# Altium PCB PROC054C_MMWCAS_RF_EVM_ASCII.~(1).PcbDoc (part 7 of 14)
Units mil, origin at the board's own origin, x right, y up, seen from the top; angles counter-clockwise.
Board outline 6299.21 x 5370.07 mil, 8 copper layers (L1 TOP, L2 GND, L3 SIGNAL 1, L4 GND, L5 SIGNAL 2, L6 SIGNAL 3, L7 GND, L8 BOTTOM), stack 53.5 mil thick; 775 components, 552 nets, 2648 pads, 7845 vias.
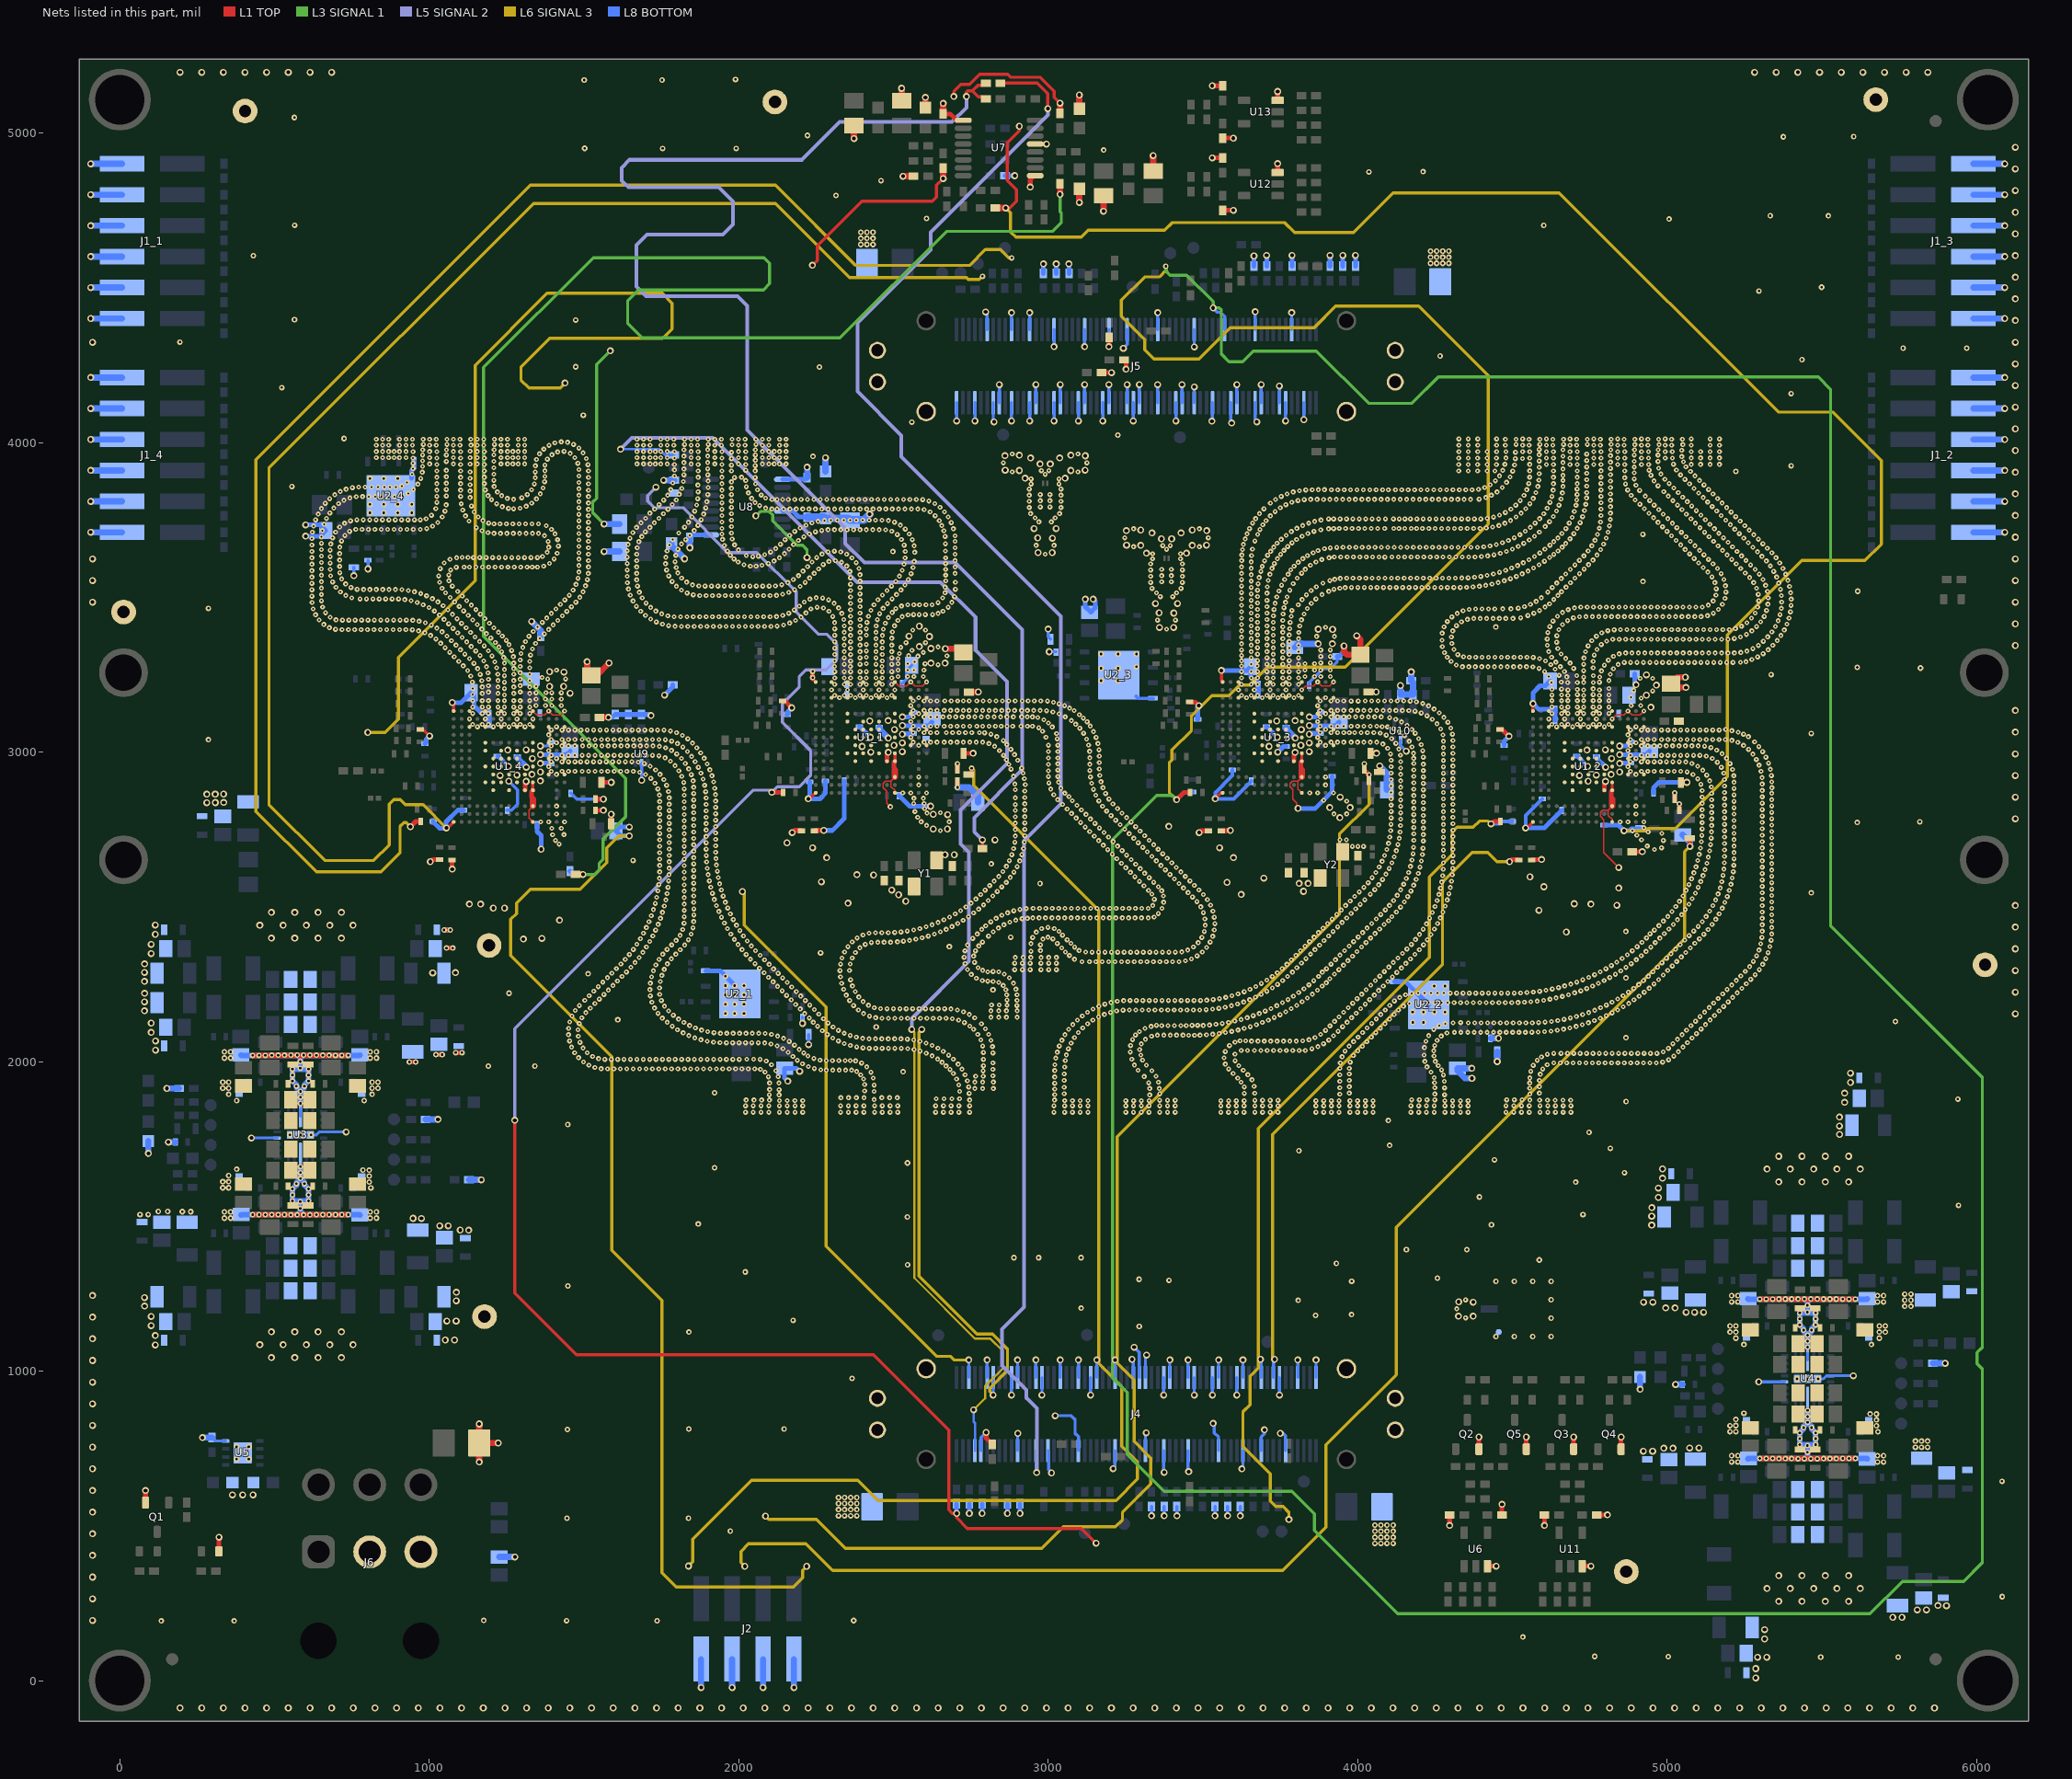
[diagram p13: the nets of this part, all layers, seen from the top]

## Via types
v1: diameter 13.77/15.74 (per signal layer), hole 5.9, L1 TOP to L2 GND, tented both sides, 5522 vias
v2: diameter 22.4, hole 12.2, L1 TOP to L8 BOTTOM, tented both sides, 1522 vias
v3: diameter 18, hole 8, L1 TOP to L8 BOTTOM, tented both sides, 727 vias
v4: diameter 18, hole 7.87, L1 TOP to L8 BOTTOM, tented top, 50 vias
v5: diameter 24, hole 12, L1 TOP to L8 BOTTOM, tented both sides, 13 vias
v6: diameter 19.68, hole 7.87, L1 TOP to L8 BOTTOM, tented top, 10 vias
v7: diameter 13.77/15.74 (per signal layer), hole 5.9, L1 TOP to L2 GND, tented top, 1 vias

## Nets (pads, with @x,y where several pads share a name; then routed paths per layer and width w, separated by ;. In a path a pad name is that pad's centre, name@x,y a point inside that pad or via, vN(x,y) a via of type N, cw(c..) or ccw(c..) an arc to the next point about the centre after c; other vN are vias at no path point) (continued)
EXT_40M_BUF_12XX_1_RS: R115.2 R116.1 R117.2 | length 5103.7
  L1 TOP w10.5: v2(2736.01,5118.34) 2736.01,5132.28 2739.95,5136.23 2755.17,5136.23 ; R116.1@2787.39,2687.68 v2(2787.39,2716.2) ; R117.2@2798.8,5110.83 2792.1,5117.53 2773.86,5117.53 2755.17,5136.23 ; R115.2@2798.8,5161.63 2792.1,5154.92 2773.86,5154.92 2755.17,5136.23
  L5 SIGNAL 2 w12: v2(2736.01,5118.34) 2736.01,5082.94 2688.92,5035.85 2325.79,5035.85 2203.61,4913.67 1647.48,4913.67 1621.64,4887.83 1621.64,4846.51 1643.5,4824.64 1935.89,4824.64 1981.39,4779.15 1981.39,4704.99 1948.57,4672.17 1703.22,4672.17 1669.07,4638.03 1669.07,4503.97 1700.69,4472.35 1996.53,4472.35 2026.88,4442 2026.88,4040.78 2343.82,3723.84 2343.82,3674.27 2405.7,3612.4 2698.66,3612.4 2916.05,3395.01 2916.05,2943.41 2761.03,2788.4 2761.03,2742.56 v2(2787.39,2716.2)
EXT_40MHZ_CLK_1V8: J4.74 R115.1 | length 5346.8
  L1 TOP w10.5: R115.1@2846.05,5161.63 2964.52,5161.63 2998.97,5127.18 v2(2998.97,5079.18)
  L5 SIGNAL 2 w12: v2(2963,672) 2963,879.16 2928.83,913.32 2928.83,939.35 2850.75,1017.44 2850.75,1135.48 2922.54,1207.28 2922.54,2714.26 3040.77,2832.49 3040.77,3438.97 2525.51,3954.23 2525.51,4022.96 2383.71,4164.76 2383.71,4386.29 2620.11,4622.69 2620.11,4679.15 2998.97,5058 v2(2998.97,5079.18)
  L8 BOTTOM w7.75: J4.74@2960.12,743.02 2960.12,674.88 v2(2963,672)
EXT_DIG_SYNC: J4.64 R142.1 | length 4659.5
  L5 SIGNAL 2 w12: v2(1617.95,3978.76) 1654.84,4015.65 1916.04,4015.65 2382.45,3549.24 2651.16,3549.24 2765.25,3435.16 2765.25,3329.43 2866.54,3228.13 2866.54,2963.13 2717.14,2813.73 2717.14,2702.79 2743.58,2676.34 2743.58,2323.96 2558.87,2139.25 v2(2558.87,2104.18)
  L6 SIGNAL 3 w6.9: v2(2558.87,2104.18) 2567.52,2095.53 2567.52,1300.82 2763.82,1104.52 2813.76,1104.52 2853.47,1064.81 2853.47,1008.41 2796.02,950.96 2796.02,912.03 v2(2759,875)
  L8 BOTTOM w7.75: v2(1617.95,3978.76) 1743.32,3978.76 1761.79,3960.29 R142.1@1791.14,3960.29 ; v2(2759,875) 2759,837 2763.27,832.73 J4.64@2763.27,743.02
GND: C1_1.2 C1_2.2 C1_3.2 C1_4.2 C2_1.2 C2_2.2 C2_3.2 C2_4.2 C3_1.2 C3_2.2 C3_3.2 C3_4.2 C4_1.2 C4_2.2 C4_3.2 C4_4.2 C5_1.2 C5_2.2 C5_3.2 C5_4.2 C6_1.2 C6_2.2 C6_3.2 C6_4.2 C7_1.2 C7_2.2 C7_3.2 C7_4.2 C8_1.2 C8_2.2 C8_3.2 C8_4.2 C9.2 C10.2 C11.2 C12.2 C13.2 C14.2 C15.2 C16.2 C17.2 C18.2 C19.2 C20.2 C21.2 C22.2 C23.2 C24.2 C25.2 C26.2 C27.2 C28.2 C29.2 C30.2 C31.2 C32.2 C33.2 C34.2 C35.2 C36.2 C39.2 C40.2 C41.2 C42.2 C43.2 C44.2 C45.2 C46.2 C47.2 C48.2 C51.2 C52.2 C53.2 C54.2 C55.2 C56.2 C57.2 C58.2 C59.2 C60.2 C61.2 C62.2 C63.2 C64.2 C65.2 C66.2 C67.2 C68.2 C69.2 C70.2 C71.2 C72.2 C73.2 C74.2 C75.2 C76.2 C77.2 C78.2 C79.2 C80.2 C81.2 C82.2 C83.2 C84.2 C85.2 C86.2 C87.2 C88.2 C89.2 C90.2 C91.2 C92.2 C93.2 C94.2 C97.2 C98.2 C99.2 C100.2 C101.2 C102.2 C103.2 C104.2 C105.2 C106.2 C109.2 C110.2 C111.2 C112.2 C113.2 C114.2 C115.2 C116.2 C117.2 C118.2 C119.2 C120.2 C121.2 C122.2 C123.2 C124.2 C125.2 C126.2 C127.2 C128_1.2 C128_2.2 C128_3.2 C128_4.2 C129_1.2 C129_2.2 C129_3.2 C129_4.2 C130_1.2 C130_2.2 C130_3.2 C130_4.2 C131_1.2 C131_2.2 C131_3.2 C131_4.2 C132_1.2 C132_2.2 C132_3.2 C132_4.2 C133_1.2 C133_2.2 C133_3.2 C133_4.2 C134_1.2 C134_2.2 C134_3.2 C134_4.2 C135_1.2 C135_2.2 C135_3.2 C135_4.2 C136_1.2 C136_2.2 C136_3.2 C136_4.2 C137_1.2 C137_2.2 C137_3.2 C137_4.2 C138_1.2 C138_2.2 C138_3.2 C138_4.2 C139_1.2 C139_2.2 C139_3.2 C139_4.2 C140_1.2 C140_2.2 C140_3.2 C140_4.2 C141_1.2 C141_2.2 C141_3.2 C141_4.2 C142_1.2 C142_2.2 C142_3.2 C142_4.2 C143_1.2 C143_2.2 C143_3.2 C143_4.2 C144_1.2 C144_2.2 C144_3.2 C144_4.2 C145_1.2 C145_2.2 C145_3.2 C145_4.2 C146_1.2 C146_2.2 C146_3.2 C146_4.2 C147_1.2 C147_2.2 C147_3.2 C147_4.2 C148_1.2 C148_2.2 C148_3.2 C148_4.2 C149.2 C150.2 C151.2 C152.2 C153.2 C154.2 C155.2 C156.2 C157.2 C158.2 C159.2 C160.2 C161.2 C162.2 C163.2 C164.2 C165.2 C166.2 C167.2 C168.1 C169.2 C170.2 C171.1 C172.2 C173.2 C174.2 C175.2 C176.2 C177.2 C178.1 C179.2 C180.1 C181.2 C182.2 C183.1 C184.2 C185.2 C186.2 C187.1 C188.2 C189.1 C190.2 C191.2 C192.2 C193.2 C194.2 C195.2 C196.2 C197.2 C198.2 C199.2 C200.2 C201.2 C202.2 C203.2 C204.2 C205.2 C206.2 C207.2 DS1.2 J1_1.2 J1_1.4 J1_1.6 J1_1.8 J1_1.10 J1_1.12 J1_2.2 J1_2.4 J1_2.6 J1_2.8 J1_2.10 J1_2.12 J1_3.2 J1_3.4 J1_3.6 J1_3.8 J1_3.10 J1_3.12 J1_4.2 J1_4.4 J1_4.6 J1_4.8 J1_4.10 J1_4.12 J2.2 J2.4 J2.6 J2.8 J3.2 J4.3 J4.6 J4.7 J4.10 J4.11 J4.14 J4.15 J4.18 J4.21 J4.23 J4.24 J4.27 J4.30 J4.31 J4.32 J4.35 J4.36 J4.39 J4.40 J4.43 J4.44 J4.47 J4.48 J4.51 J4.53 J4.54 J4.57 J4.60 J4.65 J4.71 J4.76 J4.81 J4.87 J4.92 J4.95 J4.99 J4.104 J4.108 J4.111 J4.115 J4.MH1 J4.MH2 J4.P1 J4.P2 J5.6 J5.10 J5.13 J5.17 J5.22 J5.26 J5.29 J5.34 J5.40 J5.45 J5.50 J5.56 J5.61 J5.64 J5.67 J5.68 J5.70 J5.73 J5.74 J5.77 J5.78 J5.81 J5.82 J5.85 J5.86 J5.89 J5.90 J5.91 J5.94 J5.97 J5.98 J5.100 J5.103 J5.106 J5.107 J5.110 J5.111 J5.114 J5.115 J5.118 J5.MH1 J5.MH2 J5.P3 J5.P4 J6.2 J6.3 Q1.2 Q2.2 Q3.2 Q4.2 Q5.2 R16_1.1 R16_2.1 R16_3.1 R16_4.1 R17_1.1 R17_2.1 R17_3.1 R17_4.1 R18_1.1 R18_2.1 R18_3.1 R18_4.1 R20.1 R36.1 R39.1 R40.1 R41.1 R42.1 R55.1 R57.1 R58.1 R60.1 R63.1 R64.1 R65.1 R66.1 R79.2 R81.1 R82.2 R83.2 R84.2 R85.2 R110.1 R111.1 R113.1 R124.1 R128.2 R129.1 R130.1 R131.1 R139.1 R144.1 R165.1 R182_1.1 R182_2.1 R182_3.1 R182_4.1 R183_1.1 R183_2.1 R183_3.1 R183_4.1 R184_1.1 R184_2.1 R184_3.1 R184_4.1 R185_1.1 R185_2.1 R185_3.1 R185_4.1 TP16.1 TP17.1 TP18.1 TP19.1 TP20.1 TP25.1 TP29.1 TP30.1 U1_1.A1 U1_1.A3 U1_1.A5 U1_1.A7 U1_1.A9 U1_1.A15 U1_1.B3 U1_1.B5 U1_1.B7 U1_1.B9 U1_1.B13 U1_1.B14 U1_1.C1 U1_1.C3 U1_1.C4 U1_1.C5 U1_1.C6 U1_1.C7 U1_1.C8 U1_1.C9 U1_1.C15 U1_1.D15 U1_1.E1 U1_1.E2 U1_1.E3 U1_1.E5 U1_1.E6 U1_1.E8 U1_1.E10 U1_1.E11 U1_1.E13 U1_1.E15 U1_1.F3 U1_1.F9 U1_1.F11 U1_1.G1 U1_1.G2 U1_1.G3 U1_1.G6 U1_1.G7 U1_1.G8 U1_1.G10 U1_1.H3 U1_1.H7 U1_1.H9 U1_1.H11 U1_1.J1 U1_1.J2 U1_1.J3 U1_1.J6 U1_1.J7 U1_1.J8 U1_1.J10 U1_1.K3 U1_1.K7 U1_1.K8 U1_1.K9 U1_1.K10 U1_1.K11 U1_1.L1 U1_1.L2 U1_1.L3 U1_1.L5 U1_1.L6 U1_1.L8 U1_1.L10 U1_1.M3 U1_1.N1 U1_1.N2 U1_1.N3 U1_1.R1 U1_1.R15 U1_2.A1 U1_2.A3 U1_2.A5 U1_2.A7 U1_2.A9 U1_2.A15 U1_2.B3 U1_2.B5 U1_2.B7 U1_2.B9 U1_2.B13 U1_2.B14 U1_2.C1 U1_2.C3 U1_2.C4 U1_2.C5 U1_2.C6 U1_2.C7 U1_2.C8 U1_2.C9 U1_2.C15 U1_2.D15 U1_2.E1 U1_2.E2 U1_2.E3 U1_2.E5 U1_2.E6 U1_2.E8 U1_2.E10 U1_2.E11 U1_2.E13 U1_2.E15 U1_2.F3 U1_2.F9 U1_2.F11 U1_2.G1 U1_2.G2 U1_2.G3 U1_2.G6 U1_2.G7 U1_2.G8 U1_2.G10 U1_2.H3 U1_2.H7 U1_2.H9 U1_2.H11 U1_2.J1 U1_2.J2 U1_2.J3 U1_2.J6 U1_2.J7 U1_2.J8 U1_2.J10 U1_2.K3 U1_2.K7 U1_2.K8 U1_2.K9 U1_2.K10 U1_2.K11 U1_2.L1 U1_2.L2 U1_2.L3 U1_2.L5 U1_2.L6 U1_2.L8 U1_2.L10 U1_2.M3 U1_2.N1 U1_2.N2 U1_2.N3 U1_2.R1 U1_2.R15 U1_3.A1 U1_3.A3 U1_3.A5 U1_3.A7 U1_3.A9 U1_3.A15 U1_3.B3 U1_3.B5 U1_3.B7 U1_3.B9 U1_3.B13 U1_3.B14 U1_3.C1 U1_3.C3 U1_3.C4 U1_3.C5 U1_3.C6 U1_3.C7 U1_3.C8 U1_3.C9 U1_3.C15 U1_3.D15 U1_3.E1 U1_3.E2 U1_3.E3 U1_3.E5 U1_3.E6 U1_3.E8 U1_3.E10 U1_3.E11 U1_3.E13 U1_3.E15 U1_3.F3 U1_3.F9 U1_3.F11 U1_3.G1 U1_3.G2 U1_3.G3 U1_3.G6 U1_3.G7 U1_3.G8 U1_3.G10 U1_3.H3 U1_3.H7 U1_3.H9 U1_3.H11 U1_3.J1 U1_3.J2 U1_3.J3 U1_3.J6 U1_3.J7 U1_3.J8 U1_3.J10 U1_3.K3 U1_3.K7 U1_3.K8 U1_3.K9 U1_3.K10 U1_3.K11 U1_3.L1 U1_3.L2 U1_3.L3 U1_3.L5 U1_3.L6 U1_3.L8 U1_3.L10 U1_3.M3 U1_3.N1 U1_3.N2 U1_3.N3 U1_3.R1 U1_3.R15 U1_4.A1 U1_4.A3 U1_4.A5 U1_4.A7 U1_4.A9 U1_4.A15 U1_4.B3 U1_4.B5 U1_4.B7 U1_4.B9 U1_4.B13 U1_4.B14 U1_4.C1 U1_4.C3 U1_4.C4 U1_4.C5 U1_4.C6 U1_4.C7 U1_4.C8 U1_4.C9 U1_4.C15 U1_4.D15 U1_4.E1 U1_4.E2 U1_4.E3 U1_4.E5 U1_4.E6 U1_4.E8 U1_4.E10 U1_4.E11 U1_4.E13 U1_4.E15 U1_4.F3 U1_4.F9 U1_4.F11 U1_4.G1 U1_4.G2 U1_4.G3 U1_4.G6 U1_4.G7 U1_4.G8 U1_4.G10 U1_4.H3 U1_4.H7 U1_4.H9 U1_4.H11 U1_4.J1 U1_4.J2 U1_4.J3 U1_4.J6 U1_4.J7 U1_4.J8 U1_4.J10 U1_4.K3 U1_4.K7 U1_4.K8 U1_4.K9 U1_4.K10 U1_4.K11 U1_4.L1 U1_4.L2 U1_4.L3 U1_4.L5 U1_4.L6 U1_4.L8 U1_4.L10 U1_4.M3 U1_4.N1 U1_4.N2 U1_4.N3 U1_4.R1 U1_4.R15 U2_1.4 U2_1.9 U2_2.4 U2_2.9 U2_3.4 U2_3.9 U2_4.4 U2_4.9 U3.4 U3.11 U3.17 U3.24 U3.27 U4.4 U4.11 U4.17 U4.24 U4.27 U5.4 U5.9 U6.3 U7.1 U7.9 U7.13 U8.1 U8.9 U8.13 U9.2 U10.2 U11.3 U12.3 U13.3 Y1.2 Y1.4 Y2.2 Y2.4 | length 97013.7
  L1 TOP w4: U1_4.E15@1334.67,2774.36 1322.17,2786.86 1322.17,2812.15 U1_4.E13@1335.11,2825.1 ; U1_4.E1@1334.67,3132.63 1347.46,3119.83 1373.04,3119.83 v1(1385.84,3132.63) 1398.64,3119.83 1424.22,3119.83 v1(1437.02,3132.63) ; v3(2490.03,2823.1) 2478.83,2834.3 2478.83,2873.17 2466.58,2885.42 2466.58,2899.13 2473.9,2906.45 2491.87,2906.45 ; U1_1.E15@2504.67,2868.36 2504.66,2876.28 2492.16,2888.78 2492.16,2906.16 U1_1.E13@2505.11,2919.1 ; U1_1.E1@2504.67,3226.63 2517.46,3213.83 2543.04,3213.83 v1(2555.84,3226.63) 2568.64,3213.83 2594.22,3213.83 v1(2607.02,3226.63) ; 3806.87,2906.45 3788.9,2906.45 3781.58,2899.13 3781.58,2888.42 3790.01,2879.99 3790.01,2876.99 3790.32,2876.68 3790.32,2847.83 3802.07,2836.08 3802.07,2823.61 v2(3807.43,2818.25) ; 3806.86,2906.75 U1_3.E13@3819.66,2919.55 ; 3807.16,2906.16 3807.16,2880.87 U1_3.E15@3819.67,2868.36 ; v1(3819.65,3201.04) 3832.45,3213.83 3858.04,3213.83 v1(3870.84,3226.63) 3883.64,3213.83 3909.22,3213.83 v1(3922.02,3226.63) ; 4809.87,2812.45 4791.9,2812.45 4784.58,2805.13 4784.58,2792.42 4795.84,2781.16 4795.84,2675.16 v2(4844,2627) ; U1_2.E15@4822.67,2774.36 4822.66,2782.04 4810.16,2794.54 4810.16,2813.04 U1_2.E13@4822.67,2825.54 ; v1(4822.65,3107.04) 4835.45,3119.83 4861.04,3119.83 v1(4873.84,3132.63) 4886.64,3119.83 4912.22,3119.83 v1(4925.02,3132.63)
  L1 TOP w10: C142_4.2@971.49,3073.71 979.29,3073.71 v2(1001,3052) ; v2(1055,2755) 1059.39,2755 U1_4.R15@1078.76,2774.36 ; v2(1074,3160) 1074,3159 1078.76,3154.24 U1_4.R1@1078.76,3132.63 ; v2(1276.21,1810.62) 1276.21,1252.63 1475.45,1053.39 2435.03,1053.39 2678.72,809.71 2678.72,551.71 2690.15,540.28 v2(2704.21,540.28) 2704.21,526.22 2739.03,491.4 3107.72,491.4 v2(3154.94,444.18) ; U1_4.E11@1334.67,2876.72 U1_4.E10@1334.67,2902.31 ; v2(2225,2849) 2229.39,2849 U1_1.R15@2248.76,2868.36 ; v2(2238.18,4572.97) 2253.52,4588.31 2253.52,4635.76 2397.99,4780.23 2625.19,4780.23 2638.72,4793.75 2638.72,4831.4 v2(2660.57,4853.25) ; v3@2238.94,3236.45 U1_1.R1@2248.76,3226.63 ; U1_1.E11@2504.67,2970.72 U1_1.E10@2504.67,2996.31 ; v2(2694.72,5118.56) 2694.72,5134.48 2718.04,5157.8 2746.02,5157.8 2778.24,5190.02 2869.82,5190.02 2879.64,5180.2 2974.34,5180.2 3019.01,5135.53 3019.01,5116.08 v2(3038.3,5096.79) ; v2(2862.9,4758.04) 2875.91,4758.04 2897.22,4779.35 2897.22,4816.55 2867.45,4846.32 2867.45,4968.24 2906.95,5007.73 v2(2906.95,5022.04) ; v2(3540,2849) 3559.37,2868.37 U1_3.R15@3563.76,2868.36 ; v2(3560,3264) 3560,3230.39 U1_3.R1@3563.76,3226.63 ; U1_3.E11@3819.67,2970.72 U1_3.E10@3819.67,2996.31 ; v2(4543,2755) 4547.39,2755 U1_2.R15@4566.76,2774.36 ; U1_2.R1@4566.76,3132.63 v2(4566.76,3157) ; U1_2.E11@4822.67,2876.73 U1_2.E10@4822.67,2902.32
  L1 TOP w15: Q1.2@83.04,575.13 v2(83.04,614.28) ; DS1.2@320.44,417.61 v2(320.44,463.54) ; v3(935.65,1998.68) v3(955.73,1998.68) ; v2(938.8,2759) 955.8,2776 C146_4.2@972.8,2776 ; v2(1003,2646) 1010,2653 C147_4.2@1033,2653 ; v3(1021.36,2022.88) v3(1041.44,2022.88) ; v3(1047.77,2425.1) v3(1067.85,2425.1) ; v3(1055.74,2366.96) v3(1075.82,2366.96) ; v2(1074,2621.58) C143_4.2@1074,2651.58 ; v3(1085.39,2028.93) v3(1105.47,2028.93) ; U1_4.F11@1309.07,2876.72 1309.07,2901.28 v2(1313.09,2905.3) ; 1334.66,2848.26 1334.66,2851.79 1331.09,2855.36 1331.09,2873.16 U1_4.E11@1334.67,2876.72 ; C132_4.2@1536.84,2812.06 v2(1562.37,2812.06) ; C131_4.2@1536.84,2848.02 v2(1562.37,2848.02) ; C3_4.2@1553.47,2902.31 C3_4.2@1556.55,2902.31 v2(1587.65,2902.31) ; C1_4.2@1587.76,2768.38 v2(1587.76,2799.08) ; v2(2107,2870) C146_1.2@2143.58,2870 ; C142_1.2@2141.49,3165.71 2148.29,3165.71 v2(2171,3143) ; v2(2173,2740) 2180,2747 C147_1.2@2203,2747 ; v3@2238.94,3236.45 v3(2238.94,3240.84) v3(2238.94,3260.92) ; C143_1.2@2244,2747 v2(2275,2747) ; U1_1.F11@2479.07,2970.72 2479.07,2995.28 v2(2483.09,2999.3) ; 2504.66,2942.26 2504.66,2945.79 2501.09,2949.36 2501.09,2967.16 U1_1.E11@2504.67,2970.72 ; C170.2@2660.57,5062.11 2683.18,5062.11 2703.79,5041.49 U7.1@2725.57,5041.49 ; v3(2706.84,2885.69) C132_1.2@2706.84,2906.06 ; C131_1.2@2706.84,2942.02 v3(2706.84,2962.39) ; C3_1.2@2726.55,2996.31 v2(2757.65,2996.31) ; C1_1.2@2742.78,2927.55 2748.78,2927.55 2752.78,2931.55 v3(2752.78,2947.92) ; v2(2799.43,801.89) 2799.43,783.81 R184_1.1@2820,763.24 ; v2(2942.06,4825.56) 2942.06,4849.52 2954.9,4862.36 U7.9@2957.85,4862.36 ; U7.13@2957.85,4964.72 v2(2994.73,4964.72) ; R182_4.1@3172.29,4226.15 v2(3204.44,4226.15) ; v2(3196.34,4310.12) R184_4.1@3196.34,4340.03 ; R183_4.1@3245.29,4267.15 3251.46,4260.98 v2(3251.46,4237.17) ; v2(3415,2845.99) 3439,2869.99 C146_3.2@3458.58,2870 ; C142_3.2@3457.49,3161.29 3475.71,3161.29 v2(3487,3150) ; v2(3488,2739.99) 3493.59,2745.58 C147_3.2@3518,2745.58 ; v2(3530.11,4919.87) C94.2@3564.27,4919.87 ; v2(3530.11,5152.92) C149.2@3564.27,5152.92 ; C143_3.2@3559,2745.58 3575.34,2745.58 3576.75,2746.99 v2(3589,2746.99) ; C164.2@3564.27,4750.58 v2(3598.42,4750.58) ; C165.2@3564.27,4983.63 v2(3598.42,4983.63) ; U12.3@3741.51,4872.63 v2(3741.51,4901.32) ; U13.3@3741.51,5105.67 v2(3741.51,5134.37) ; U1_3.F11@3794.07,2970.72 3794.07,2995.28 v2(3798.09,2999.3) ; 3819.66,2942.26 3819.66,2945.79 3816.09,2949.36 3816.09,2967.16 U1_3.E11@3819.67,2970.72 ; v3(4021.84,2962.39) C132_3.2@4021.84,2942.02 4021.84,2941.43 v3(4036.84,2926.43) C131_3.2@4036.84,2906.06 ; C4_3.2@4035.05,3194.3 v2(4060.01,3194.3) ; v2(4297.35,501.48) C162.2@4297.35,535.63 ; Q2.2@4391.79,747.96 v2(4391.79,787.12) ; U6.3@4419.39,369.58 v2(4447.63,369.58) ; v2(4431,2767.99) 4434,2767.99 4442,2775.99 C146_2.2@4461.58,2776 ; C143_2.2@4459.99,3073.71 4466.29,3073.71 v2(4489,3051) ; C205.2@4466.64,535.63 v2(4466.64,569.79) ; v2(4491,2646) 4498,2653 C147_2.2@4521,2653 ; Q5.2@4545.01,747.96 v2(4545.01,787.12) ; C142_2.2@4562,2653 v2(4594.6,2653) ; v2(4603.8,501.48) C163.2@4603.8,535.63 ; Q3.2@4698.24,747.96 v2(4698.24,787.12) ; U11.3@4725.84,369.58 v2(4754.08,369.58) ; C206.2@4773.09,535.63 v2(4807.24,535.63) ; U1_2.F11@4797.07,2876.73 4797.07,2901.28 v2(4801.09,2905.3) ; 4822.66,2848.26 4822.66,2851.79 4819.09,2855.36 4819.09,2873.16 U1_2.E11@4822.67,2876.73 ; Q4.2@4851.46,747.96 v2(4851.46,787.12) ; R129.1@4887.26,2678.08 v2(4919.89,2678.08) ; C131_2.2@5024.84,2848.02 v3(5024.84,2868.39) ; C132_2.2@5039.84,2812.06 v3(5039.84,2832.43) ; v2(5074.3,2695.45) C1_2.2@5074.3,2721.83
  L1 TOP w18: v3(429.13,1505.67) v3(449.72,1505.67) v3(470.3,1505.67) v3(696.77,1505.67) v3(717.36,1505.67) v3(737.95,1505.67) ; v3(429.13,2020.25) v3(449.72,2020.25) v3(470.3,2020.25) v3(696.77,2020.25) v3(717.36,2020.25) v3(737.95,2020.25) ; v3(5299.85,717.82) v3(5320.44,717.82) v3(5341.03,717.82) v3(5567.5,717.82) v3(5588.08,717.82) v3(5608.67,717.82) ; v3(5299.85,1232.4) v3(5320.44,1232.4) v3(5341.03,1232.4) v3(5567.5,1232.4) v3(5588.08,1232.4) v3(5608.67,1232.4)
  L1 TOP w20: v2(1161.36,706.2) C194.2@1161.36,767.73 ; v2(1161.36,829.27) C194.2@1161.36,767.73 ; v2(1222.9,767.73) C194.2@1161.36,767.73 ; U1_4.E13@1334.66,2825.55 1334.66,2848.26 ; R131.1@1472.35,2604.99 1472.48,2604.86 v2(1496.6,2604.86) ; v2(1510,3292) 1510,3261.9 C5_4.2@1523.9,3248 1541.11,3248 v2(1581,3287.89) ; C4_4.2@1550.05,3112.3 v2(1579.01,3112.3) ; v2(2372.39,4982.34) C169.2@2372.39,5024.49 ; U1_1.E13@2504.66,2919.55 2504.66,2942.26 ; C172.2@2526.41,5104.49 v2(2526.41,5144.71) ; v2(2531.11,4860.7) R111.1@2564.74,4860.7 ; C171.1@2603.2,5081.97 v2(2603.2,5115.2) ; v2(2660.57,4853.25) R113.1@2660.57,4886.89 ; C170.2@2660.57,5062.11 v2(2660.57,5095.75) ; v2(2667.72,3333.88) 2708.69,3333.88 C5_1.2@2720.58,3321.99 ; C4_1.2@2743.75,3194.3 v2(2774.01,3194.3) ; R124.1@2829.26,4758.04 v2(2862.9,4758.04) ; v2(3038.3,4802.35) C177.2@3038.3,4835.99 ; C179.2@3038.3,5063.15 v2(3038.3,5096.79) ; v2(3100.57,4775.82) C180.1@3100.57,4820.24 ; C178.1@3100.57,5078.9 v2(3100.57,5123.32) ; v2(3178.88,4747.74) C176.2@3178.88,4797.72 ; C175.2@3339.25,4877.72 v2(3339.25,4927.69) ; U1_3.E13@3819.66,2919.55 3819.66,2942.26 ; v2(3956.01,3343) 3956.01,3324.56 3965.57,3315 C5_3.2@4008.9,3315 4008.9,3364.11 v2(3997.01,3376) ; C3_3.2@4041.55,2996.31 v2(4060.98,2996.31) ; C1_3.2@4071.3,2935.83 v2(4071.3,2955.26) ; U1_2.E13@4822.66,2825.55 4822.66,2848.26 ; C5_2.2@5023.9,3209 C5_2.2@5024.4,3209 ; C5_2.2@5032.9,3242 C5_2.2@5033.4,3242 ; C3_2.2@5044.55,2902.32 v2(5063.98,2902.32) ; v2(5059.01,3242) C5_2.2@5033.4,3242 ; v2(5061.01,3209) C5_2.2@5024.4,3209 ; C5_2.2@5024.4,3209 C5_2.2@5012.4,3221 C5_2.2@5033.4,3242
  L3 SIGNAL 1 w10: v2(1496.6,2604.86) 1534.82,2604.86 1549.07,2619.11 1549.07,2640.97 1561.74,2653.64 1561.74,2718.45 1634.19,2790.89 1634.19,2915.19 1175.4,3373.98 1175.4,4242.81 1530.09,4597.5 2081.24,4597.5 2099.91,4578.84 2099.91,4513.4 2079.86,4493.35 1675.38,4493.35 1641.2,4459.18 1641.2,4385.13 1688.16,4338.17 2327.35,4338.17 2671.64,4682.46 3012.93,4682.46 3042.49,4712.01 3042.49,4741.62 3038.3,4745.81 v2(3038.3,4802.35) ; v2(1565.04,3737.01) 1528.14,3773.91 1528.14,3807.93 1540.62,3820.41 1540.62,4252.03 v2(1585.07,4296.48) ; v2(2055.22,3763.57) 2069.16,3777.51 2098.33,3777.51 2109.76,3766.07 2109.76,3747.19 2189.11,3667.84 2206.82,3667.84 2220.6,3654.06 v2(2220.6,3628.64) ; v3(3380.12,4569.57) 3380.12,4554.81 3394.25,4540.68 3447.6,4540.68 3533,4455.28 v2(3533,4435) 3553.28,4435 3559.52,4428.76 3559.52,4286.36 3584.58,4261.29 3627.97,4261.29 3662.27,4295.59 3866.56,4295.59 4035.24,4126.91 4175.52,4126.91 4260.9,4212.29 5488.71,4212.29 5528.29,4172.71 5528.29,2439.34 6018.9,1948.73 6018.9,1076.4 6002.23,1059.73 6002.23,1024 6018.9,1007.33 6018.9,380.58 5959.18,320.85 5760.45,320.85 5656.07,216.48 4129.23,216.48 3860.56,485.15 3860.56,538.76 3788.12,611.2 3375.2,611.2 3255.87,730.52 3255.87,930.64 3208.58,977.94 3208.58,1028.58 v2(3216.02,1036.02) 3208.58,1043.46 3208.58,2717.91 3350.1,2859.43 3401.56,2859.43 v2(3415,2845.99)
  L3 SIGNAL 1 w15: v3(935.65,1998.68) v3(955.73,1998.68) ; v3(1021.36,2022.88) v3(1041.44,2022.88) ; v3(1047.77,2425.1) v3(1067.85,2425.1) ; v3(1055.74,2366.96) v3(1075.82,2366.96) ; v3(1085.39,2028.93) v3(1105.47,2028.93) ; v3(2238.94,3240.84) v3(2238.94,3260.92)
  L5 SIGNAL 2 w10: v2(1276.21,1810.62) 1276.21,2105.92 2047.4,2877.11 2099.45,2877.11 v2@2105.97,2870.6 ; v2(1732.45,3856.27) 1705.55,3829.37 1705.55,3811 1727.03,3789.52 1820.05,3789.52 1964.61,3644.96 2058.58,3644.96 2185.32,3518.22 2185.32,3452.29 2256.62,3380.99 2284.38,3380.99 2317.07,3348.29 2317.07,3300.46 2282.56,3265.94 2217.15,3265.94 2195.43,3244.22 2195.43,3210.51 2140.68,3155.76 2140.68,3096.7 2232.53,3004.84 2232.53,2924.69 2196.25,2888.41 2125.41,2888.41 v2(2107,2870)
  L5 SIGNAL 2 w15: v3(935.65,1998.68) v3(955.73,1998.68) ; v3(1021.36,2022.88) v3(1041.44,2022.88) ; v3(1047.77,2425.1) v3(1067.85,2425.1) ; v3(1055.74,2366.96) v3(1075.82,2366.96) ; v3(1085.39,2028.93) v3(1105.47,2028.93) ; v3(2238.94,3240.84) v3(2238.94,3260.92)
  L6 SIGNAL 3 w10: v2(800.96,3063.54) 857.27,3063.54 900.58,3106.85 900.58,3306.44 1148.11,3553.97 1148.11,4249.67 1380.83,4482.39 1753.08,4482.39 1784.95,4450.52 1784.95,4367.49 1754.07,4336.61 1389.3,4336.61 1296.19,4243.5 1296.19,4202.42 1322.01,4176.6 1422.88,4176.6 v2(1438.59,4192.31) ; v2(938.8,2759) 925.98,2771.82 917.41,2771.82 905.29,2759.7 905.29,2674.52 843.54,2612.77 635.13,2612.77 439.66,2808.24 439.66,3944.35 1326.79,4831.48 2119.06,4831.48 2378.11,4572.43 2745.55,4572.43 2797.04,4623.91 2845.35,4623.91 2872.26,4597 v3(2882.47,4597) ; v2(1055,2755) 979.95,2830.05 922.89,2830.05 905.99,2846.95 885.8,2846.95 870.48,2831.63 870.48,2700.12 820.22,2649.86 662.67,2649.86 481.81,2830.73 481.81,3917.49 1337,4772.68 2118.43,4772.68 2358.26,4532.85 2736.27,4532.85 2741.8,4527.32 2777.75,4527.32 v3(2787.89,4537.46) ; v2(1646.2,2729.28) 1611.91,2729.28 1573.26,2690.63 1573.26,2643.14 1487.15,2557.03 1326.32,2557.03 1281.89,2512.59 1281.89,2478.52 1263.19,2459.82 1263.19,2342.31 1589.62,2015.89 1589.62,1390.67 1751.66,1228.63 1751.66,348.35 1797.45,302.57 2176.93,302.57 2206.04,331.68 2206.04,355.92 v2(2219.53,369.41) ; v2(1837.36,370.15) 1851.2,383.99 1851.2,456.66 2041.89,647.35 2385.29,647.35 2450.33,582.31 3219.28,582.31 3288.03,651.06 3288.03,706.45 3237.71,756.77 3237.71,949.79 3163.31,1024.19 3163.31,2488.08 2759.34,2892.05 2759.34,2941.37 v3(2752.78,2947.92) ; v2(2011.87,2549.41) 2018.17,2543.11 2018.17,2441.17 2282.51,2176.83 2282.51,1403.81 2638.42,1047.9 2683.68,1047.9 2695.55,1036.02 v2(2743.58,1036.02) ; v2(2019.53,369.41) 2007.09,381.85 2007.09,417.61 2031.52,442.03 2217.43,442.03 2303.69,355.78 3758.2,355.77 3897.72,495.29 3897.72,761.45 4124.44,988.18 4124.45,1464.53 5056.89,2396.97 5056.89,2631.3 5056.89,2678.04 v2(5074.3,2695.45) ; v2(2086.8,531.49) 2097.08,521.21 2250.96,521.21 2345.12,427.06 2979.3,427.06 3049.53,497.28 3217.33,497.28 3240.22,520.17 3240.22,544.18 3331.72,635.68 3331.72,719.16 3277.39,773.49 3277.39,971.45 3222.47,1026.37 3222.47,1757.53 3941.28,2476.34 3941.28,2735.24 4036.84,2830.8 v3(4036.84,2926.43) ; v2(2591.52,2104.18) 2582.57,2095.24 2582.57,1307.06 2770.06,1119.57 2820,1119.57 2868.52,1071.05 2868.52,1002.17 2811.07,944.73 2811.07,933.71 v2(2822.32,922.46) ; v2(2862.9,4758.04) 2878.45,4742.49 2878.45,4680.66 2895.65,4663.46 3106.72,4663.46 3129.06,4685.81 3376,4685.81 3401,4710.81 3764.03,4710.81 3796.08,4678.76 3986.67,4678.76 4114.55,4806.64 4651.17,4806.64 5359.21,4098.6 5535.27,4098.6 5692.52,3941.35 5692.52,3671.89 5639.89,3619.25 5435.52,3619.25 5194.65,3378.39 5194.65,2920.74 5027.25,2753.34 4938.98,2753.34 4931.64,2746.01 v2(4860.82,2746.01) ; v3(3380.12,4569.57) 3380.12,4556.54 3358.95,4535.36 3311.52,4535.36 3236.66,4460.49 3236.66,4407.89 3311.84,4332.72 3311.84,4300.31 3341.54,4270.6 3488.03,4270.6 3589.08,4371.66 3859.69,4371.66 3929.25,4441.22 4197.12,4441.22 4422.08,4216.26 4422.08,3737.37 3959.34,3274.63 3709.05,3274.63 3650.78,3216.36 3618.13,3216.36 3584.06,3182.28 3528.83,3182.28 3496.55,3150 v2(3487,3150) 3487,3140.45 3463.06,3116.52 3463.06,3070.15 3399.95,3007.03 3399.95,2974.27 3391.48,2965.8 3391.48,2869.51 v2(3415,2845.99) ; v2(3731.7,1038.1) 3725.03,1044.78 3725.03,1764.63 4274.43,2314.03 4274.43,2580.67 4369.72,2675.95 4420.86,2675.95 4450.81,2646 v2(4491,2646) ; v2(3777.97,520.49) 3777.97,543.53 3759.26,562.24 3736.2,562.24 3718.05,580.39 3718.05,667.93 3629.16,756.81 3629.16,867.94 3652.2,890.97 3652.2,982.91 3679.32,1010.04 3679.32,1783.72 4231.84,2336.23 4231.84,2596.33 4305.96,2670.46 4305.96,2741.62 4321.8,2757.46 4373.57,2757.46 4393.5,2777.39 4421.6,2777.39 v2(4431,2767.99)
  L6 SIGNAL 3 w15: v3(935.65,1998.68) v3(955.73,1998.68) ; v3(1021.36,2022.88) v3(1041.44,2022.88) ; v3(1047.77,2425.1) v3(1067.85,2425.1) ; v3(1055.74,2366.96) v3(1075.82,2366.96) ; v3(1085.39,2028.93) v3(1105.47,2028.93) ; v3(2238.94,3240.84) v3(2238.94,3260.92)
  L8 BOTTOM w9: v2(425.36,1753.12) U3.17@508.73,1753.12 ; v6(583.54,1762.96) v6(617.79,1762.96) 634.44,1762.96 644.28,1772.8 U3.4@658.34,1772.8 v2(731.45,1772.8) ; v2(5296.09,965.26) U4.17@5379.46,965.26 ; v6(5454.26,975.11) v6(5488.51,975.11) 5505.16,975.11 5515.01,984.95 U4.4@5529.07,984.95 v2(5602.17,984.95)
  L8 BOTTOM w10: C9.2@297.71,785.11 308.66,774.16 U5.4@342,774.16 ; U3.24@583.54,1823.59 U3.24@583.54,1846.14 ; v2(756.26,3570.06) C7_4.2@756.26,3596.9 ; v2(802,3591.8) C8_4.2@802,3619.4 ; C135_4.2@1251.3,2812 1266.07,2812 1285.62,2831.55 1285.62,2877.38 v2(1257.08,2905.92) ; v2(1358.99,3019.7) 1379.57,3019.7 C140_4.2@1394.98,3035.11 ; C134_4.2@1457.23,2867 1476.2,2848.02 v2(1562.37,2848.02) ; v2(1686.31,2909.08) U9.2@1686.31,2964.56 ; v2(2205.91,2123.64) C8_1.2@2205.91,2143.45 ; v2(2225.91,2055.13) C7_1.2@2225.91,2087.69 ; C128_1.2@2527.72,3221.01 2542.27,3235.56 2542.27,3264.12 C130_1.2@2558.95,3280.8 ; v2(2704.21,4070.21) J5.61@2704.21,4128.84 ; J4.3@2743.58,979.24 v2(2743.58,1036.02) ; v2(2763.27,4070.21) J5.64@2763.27,4128.84 ; J4.65@2782.95,743.02 2782.95,785.41 v2(2799.43,801.89) ; v2(2798,4422) 2802.64,4417.36 J5.6@2802.64,4365.06 ; J4.6@2802.64,979.24 v2(2802.64,1036.02) ; v2(2822.32,922.46) J4.7@2822.32,979.24 ; J5.67@2822.32,4128.84 2822.32,4069.68 v2(2825,4067) ; J5.68@2842.01,4128.84 v2(2842.01,4187.47) ; v2(2881.38,922.46) J4.10@2881.38,979.24 ; v2(2881.38,4070.21) J5.70@2881.38,4128.84 ; J5.10@2881.38,4365.06 v2(2881.38,4420) ; J4.71@2901.06,743.02 2901.06,798.94 2901.12,799 v2(2902,799) ; J4.11@2901.06,979.24 v2(2901.06,1036.02) ; v2(2940.43,4070.21) J5.73@2940.43,4128.84 ; J5.13@2940.43,4365.06 v2(2940.43,4420) ; J4.14@2960.12,979.24 v2(2960.12,1036.02) ; J5.74@2960.12,4128.84 v2(2960.12,4187.47) ; v2(2979.8,922.46) J4.15@2979.8,979.24 ; J4.76@2999.49,743.02 3001,741.51 3001,681 v2(3011,671) ; v2(2999.93,3397.45) 2999.93,3372.79 C7_3.2@3007.86,3364.87 ; v2(3003.35,3324.4) C8_3.2@3025.36,3324.4 ; v2(3019.17,4070.21) J5.77@3019.17,4128.84 ; v2(3019.17,4310.12) J5.17@3019.17,4365.06 ; v2(3023,856) 3074,856 3087,843 3087,799.01 3097.91,788.1 J4.81@3097.91,743.02 ; J4.18@3038.86,979.24 v2(3038.86,1036.02) ; J5.78@3038.86,4128.84 v2(3038.86,4187.47) ; J4.21@3097.91,979.24 v2(3097.91,1036.02) ; v2(3097.91,4070.21) J5.81@3097.91,4128.84 ; J5.82@3117.6,4128.84 v2(3117.6,4187.47) ; v2(3117.6,4310.12) J5.22@3117.6,4365.06 ; v2(3137.28,922.46) J4.23@3137.28,979.24 ; J4.24@3156.97,979.24 v2(3156.97,1036.02) ; v2(3176.65,4070.21) J5.85@3176.65,4128.84 ; J5.86@3196.34,4128.84 v2(3196.34,4187.47) ; v2(3196.34,4310.12) J5.26@3196.34,4365.06 ; v2(3210,685) 3216.02,691.02 J4.87@3216.02,743.02 ; J4.27@3216.02,979.24 v2(3216.02,1036.02) ; v2(3243,4305) 3255.39,4317.39 J5.29@3255.39,4365.06 ; J5.89@3255.39,4128.84 v2(3255.39,4187.47) ; v2(3271,1038) 3271,1036 3275.08,1031.92 J4.30@3275.08,979.24 ; v2(3275.08,4070.21) J5.90@3275.08,4128.84 ; v2(3278,1077) 3294.76,1060.24 J4.31@3294.76,979.24 ; U2_3.9@3283,3180.95 3289.95,3174 U2_3.9@3291.91,3174 ; U2_3.9@3284.96,3180.95 U2_3.9@3291.91,3174 ; J5.91@3294.76,4128.84 v2(3294.76,4187.47) ; J4.92@3314.45,743.02 3314.45,798.94 3314.94,798.94 v2(3317,801) ; J4.32@3314.45,979.24 3314.45,1048.45 v2(3318,1052) ; v2(3334,532.56) R184_2.1@3334,563.18 ; U2_3.4@3340.16,3174 U2_3.4@3338.2,3174 U2_3.9@3291.91,3174 ; J5.94@3353.82,4128.84 v2(3353.82,4187.47) ; J5.34@3353.82,4365.06 3353.82,4419.82 v2(3354,4420) ; J4.95@3373.5,743.02 3373.5,674.5 v2(3375,673) ; v2(3373.5,922.46) J4.35@3373.5,979.24 ; v2(3375,532.56) R183_2.1@3375,563.18 ; J4.36@3393.19,979.24 v2(3393.19,1036.02) ; v2(3412.87,4070.21) J5.97@3412.87,4128.84 ; v2(3416,532.56) R182_2.1@3416,563.18 ; J5.98@3432.56,4128.84 v2(3432.56,4187.47) ; J4.99@3452.24,743.02 3452.24,676.76 v2(3454,675) ; J4.39@3452.24,979.24 v2(3452.24,1036.02) ; v2(3471.93,922.46) J4.40@3471.93,979.24 ; J5.100@3471.93,4128.84 v2(3471.93,4179.75) ; v2(3471.93,4309) J5.40@3471.93,4365.06 ; v2(3529,4069) 3530.98,4070.98 J5.103@3530.98,4128.84 ; v2(3530.98,922.46) J4.43@3530.98,979.24 ; v2(3533,831) 3537,827 3537,800 3550.67,786.33 J4.104@3550.67,743.02 ; v2(3533,4435) 3547,4421 3556,4421 3570.35,4406.65 J5.45@3570.35,4365.06 ; v2(3539,532.56) R16_2.1@3539,563.18 ; J4.44@3550.67,979.24 v2(3550.67,1036.02) ; v2(3580,532.56) R17_2.1@3580,563.18 ; J5.106@3590.04,4128.84 3590.04,4065.96 v2(3593,4063) ; v2(3609.72,922.46) J4.47@3609.72,979.24 ; J5.107@3609.72,4128.84 v2(3609.72,4187.47) ; v2(3621,532.56) R18_2.1@3621,563.18 ; v2(3626.15,683.84) 3629.41,687.1 J4.108@3629.41,743.02 ; J4.48@3629.41,979.24 v2(3629.41,1036.02) ; J5.110@3668.78,4128.84 3668.78,4072.22 v2(3674,4067) ; J5.50@3668.78,4365.06 3668.78,4418.78 3669,4419 v2(3669,4423) ; v2(3686,1038) 3688.46,1035.54 J4.51@3688.46,979.24 ; J4.111@3688.46,743.02 3688.46,786.27 3699.02,796.83 v2(3699.02,810.32) ; J5.111@3688.46,4128.84 v2(3688.46,4187.47) ; J4.53@3727.83,979.24 3727.83,1034.23 v2(3731.7,1038.1) ; v2(3747,4183) 3747.52,4182.48 J5.114@3747.52,4128.84 ; v2(3747.52,922.46) J4.54@3747.52,979.24 ; v2(3750,799) 3759.45,799 3767.2,791.25 J4.115@3767.2,743.02 ; v2(3767.2,4070.21) J5.115@3767.2,4128.84 ; J5.56@3786.89,4365.06 v2(3786.89,4420) ; J4.57@3806.57,979.24 v2(3806.57,1036.02) ; v2(3826.26,4074) J5.118@3826.26,4128.84 ; C129_3.2@3842.72,3216.01 3842.72,3223.86 3888.84,3269.98 3912.76,3269.98 3933.9,3291.11 R83.2@3933.9,3308.75 ; J4.60@3865.63,979.24 v2(3865.63,1036.02) ; U10.2@4138.47,3038.55 4138.47,3021.98 v2(4157.16,3003.28) ; U4.24@5454.26,1035.74 U4.24@5454.26,1058.28
  L8 BOTTOM w12: v2(3415,2845.99) 3440.01,2871 C148_3.2@3466.95,2871 ; C145_3.2@3595.75,2942.9 3595.75,2924.6 3540,2868.85 v2(3540,2849) 3599.3,2849 C135_3.2@3656.3,2906 ; v2(4431,2767.99) 4458.17,2767.99 4465.76,2775.58 C148_2.2@4500,2775.58 ; v2(4543,2755) 4543,2795.6 C144_2.2@4596.3,2848.9
  L8 BOTTOM w15: v2(600.47,3697.65) 646.98,3697.65 C6_4.2@665.16,3715.83 646.98,3734.01 v2(600.47,3734.01) ; U2_4.9@943.11,3884.1 943.11,3909.04 950.89,3916.82 U2_4.4@950.89,3938.33 U2_4.4@950.89,3940.3 ; R185_4.1@985.9,3027 990.22,3031.32 990.22,3041.21 v2(1001,3052) ; C148_4.2@1012,2775.58 1033.31,2754.27 1054.27,2754.27 1054.27,2774.28 1092.34,2812.35 C144_4.2@1110.64,2812.35 ; v2(1074,3160) 1103,3160 C139_4.2@1135.03,3192.04 1144.92,3182.15 1144.92,3149.1 1166.4,3127.62 1191.27,3127.62 C138_4.2@1194.09,3124.8 C137_4.2@1194.09,3090.18 ; C129_4.2@1222.4,2986.99 v2(1255.39,2954) ; C145_4.2@1348.51,2765.53 1348.51,2743.47 1361.52,2730.45 v2(1361.52,2686.08) ; v2(1358.79,2963.7) 1360.18,2965.09 1389.62,2965.09 C2_4.2@1393,2961.71 ; v2(1358.99,2991.7) 1443.71,2991.7 C141_4.2@1454.98,3002.97 ; R84.2@1454.53,2615.6 1465.26,2604.86 v2(1496.6,2604.86) ; v2(1579.01,3112.3) 1591.13,3112.3 R165.1@1600.31,3121.47 C196.2@1643.31,3121.46 C195.2@1686.31,3121.45 1713.07,3121.45 v2(1716.31,3118.21) ; v2(1646.2,2729.28) 1619.35,2729.28 C133_4.2@1602.63,2745.99 1614.35,2757.71 v2(1646.2,2757.71) ; v2(1760.21,3184.24) 1786.57,3210.6 C197.2@1786.57,3217.44 ; C182.2@1841.77,3693.88 1849.72,3701.82 U8.1@1908.9,3701.82 ; U2_1.4@1893.07,2293.45 1940.27,2293.45 U2_1.9@1985.27,2248.45 ; U8.13@2141.18,3778.59 2175.06,3778.59 2194.18,3759.47 C186.2@2220.98,3759.47 ; U8.9@2141.18,3880.96 2215.27,3880.96 C188.2@2220.98,3886.67 ; R185_1.1@2155.9,3121 2160.36,3125.47 2160.36,3132.37 v2(2171,3143) ; v2(2158.35,1936.85) 2148.35,1946.85 C6_1.2@2148.35,1978.54 2186.78,1978.54 v2(2196.78,1968.54) ; C148_1.2@2229,2904.28 2229,2853 v2(2225,2849) 2261.98,2849 2280.64,2867.66 C145_1.2@2280.64,2906.35 ; v2(2275,2747) 2302.8,2747 2341.3,2785.5 C135_1.2@2341.3,2906 ; C129_1.2@2389.89,3083.11 2390.28,3083.11 v2(2425.39,3048) ; C144_1.2@2518.51,2859.53 2553.04,2825.01 v2(2619.99,2825.01) ; v2(2528.79,3057.7) 2530.18,3059.09 C2_1.2@2563.59,3059.09 ; v2(2528.99,3085.7) 2613.71,3085.7 C141_1.2@2624.98,3096.97 ; v2(2528.99,3113.7) 2549.57,3113.7 C140_1.2@2564.98,3129.11 ; v2(2704.21,540.28) R16_1.1@2704.21,570.9 ; v2(2745.21,540.28) R17_1.1@2745.21,570.9 ; v2(2786.21,540.28) R18_1.1@2786.21,570.9 ; R110.1@2860.62,4862.36 v2(2892.21,4862.36) ; v2(2868.21,540.28) R183_1.1@2868.21,570.9 ; v2(2909.21,540.28) R182_1.1@2909.21,570.9 ; R18_4.1@2985,4546.21 v2(2985,4577.44) ; R17_4.1@3026,4546.21 v2(3026,4577.44) ; R16_4.1@3067,4546.21 v2(3067,4577.44) ; v2(3119.74,3494.24) 3119.74,3470.18 3137.93,3452 3151.8,3465.88 3151.8,3487.89 v2(3145.45,3494.24) ; R185_3.1@3482.96,3106.54 3482.96,3145.96 v2(3487,3150) ; v2(3560,3264) 3642.15,3264 C139_3.2@3654.19,3276.04 3654.19,3243.7 C137_3.2@3679.09,3218.8 C138_3.2@3679.09,3184.18 ; R182_3.1@3665,4570.25 v2(3665,4603.03) ; C128_3.2@3705.79,3082.59 v2(3740.39,3048) ; R183_3.1@3706,4570.25 v2(3706,4604.76) ; v2(3742.08,2999.92) 3760.43,3018.27 C144_3.2@3769.06,3018.27 ; R184_3.1@3788,4570.25 v2(3788,4604.76) ; v2(3807.43,2818.25) 3863.13,2818.25 3918.09,2873.22 C134_3.2@3918.09,2922 ; v2(3843.79,3057.7) 3846.6,3060.51 C2_3.2@3878.59,3060.51 ; v2(3843.99,3085.7) 3928.71,3085.7 C141_3.2@3939.98,3096.97 ; v2(3843.99,3113.7) 3864.57,3113.7 C140_3.2@3879.98,3129.11 ; R18_3.1@3911,4570.25 v2(3911,4604.76) ; R83.2@3933.9,3308.75 3939.2,3308.75 3956.01,3325.55 v2(3956.01,3343) ; R17_3.1@3952,4570.25 v2(3952,4604.76) ; R16_3.1@3993,4570.25 v2(3993,4604.76) ; U2_2.4@4119.72,2258.17 4154.96,2258.17 U2_2.9@4229.96,2183.17 ; R185_2.1@4473.9,3021.05 4473.9,3035.9 v2(4489,3051) ; v2(4543,2755) 4603.72,2755 C135_2.2@4660.72,2812 ; C139_2.2@4621.99,3229.77 4606.5,3214.27 4589.48,3214.27 4566.76,3191.55 v2(4566.76,3157) 4585.61,3138.15 C138_2.2@4639,3138.15 C137_2.2@4639,3103.53 ; C129_2.2@4708.28,2989.11 v2(4743.39,2954) ; C136_2.2@4772.38,2987.49 C136_2.2@4772.38,2986.07 4772.38,2980.41 v2(4801.54,2951.25) ; C145_2.2@4796.51,2763.84 4842.99,2763.84 v2(4860.82,2746.01) 4878.71,2746.01 4885.14,2752.44 R79.2@4912.16,2752.44 ; v2(4846.79,2963.7) 4848.18,2965.09 C2_2.2@4881.59,2965.09 ; v2(4846.99,2991.7) 4931.71,2991.7 C141_2.2@4942.98,3002.97 ; v2(4846.99,3019.7) 4867.57,3019.7 C140_2.2@4882.98,3035.11 ; R82.2@4895.5,3253.5 4895.5,3221.66 v2(4899.7,3217.46) ; C134_2.2@4956.09,2868 4956.09,2885.08 4973.33,2902.32 v2(5063.98,2902.32)
  L8 BOTTOM w18: C65.2@391.09,1504.33 C65.2@392.43,1505.67 v3(429.13,1505.67) v3(449.72,1505.67) v3(470.3,1505.67) v3(696.77,1505.67) v3(717.36,1505.67) v3(737.95,1505.67) 774.64,1505.67 C62.2@775.98,1504.33 ; C68.2@391.09,2021.59 392.43,2020.25 v3(429.13,2020.25) v3(449.72,2020.25) v3(470.3,2020.25) v3(696.77,2020.25) v3(717.36,2020.25) v3(737.95,2020.25) 774.64,2020.25 C66.2@775.98,2021.59 ; v3(573.24,1504.88) 582.99,1514.63 v3(582.99,1547.37) 580.14,1550.22 v3(557.96,1550.22) v3(557.96,1569.4) v3(557.96,1588.57) 570.55,1601.17 v3(570.55,1605.34) 570.55,1609.22 v3(583.54,1622.21) ; v3(573.24,2021.04) 582.99,2011.29 v3(582.99,1978.55) 580.14,1975.71 v3(557.96,1975.71) v3(557.96,1956.53) v3(557.96,1937.35) 570.55,1924.75 v3(570.55,1920.58) 570.55,1916.7 v3(583.54,1903.71) ; 583.23,1514.63 v3@592.98,1504.88 ; 583.23,2011.29 v3@592.98,2021.04 ; v3@584.08,1547.37 586.93,1550.22 609.12,1550.22 609.12,1588.57 596.53,1601.17 596.53,1609.22 v3(583.54,1622.21) ; v3@584.08,1978.55 586.93,1975.71 609.12,1975.71 609.12,1937.35 596.53,1924.75 596.53,1916.7 v3(583.54,1903.71) ; C123.2@5261.82,716.48 C123.2@5263.16,717.82 v3(5299.85,717.82) v3(5320.44,717.82) v3(5341.03,717.82) v3(5567.5,717.82) v3(5588.08,717.82) v3(5608.67,717.82) 5645.37,717.82 C120.2@5646.71,716.48 ; C126.2@5261.82,1233.73 5263.16,1232.4 v3(5299.85,1232.4) v3(5320.44,1232.4) v3(5341.03,1232.4) v3(5567.5,1232.4) v3(5588.08,1232.4) v3(5608.67,1232.4) 5645.37,1232.4 C124.2@5646.71,1233.73 ; v3(5443.97,717.03) 5453.72,726.78 v3(5453.72,759.51) 5450.87,762.36 v3(5428.68,762.36) v3(5428.68,781.54) v3(5428.68,800.72) 5441.27,813.31 v3(5441.27,817.49) 5441.27,821.37 v3(5454.26,834.36) ; v3(5443.97,1233.18) 5453.72,1223.44 v3(5453.72,1190.7) 5450.87,1187.85 v3(5428.68,1187.85) v3(5428.68,1168.67) v3(5428.68,1149.49) 5441.27,1136.9 v3(5441.27,1132.73) 5441.27,1128.85 v3(5454.26,1115.86) ; 5453.95,726.78 v3@5463.7,717.03 ; 5453.95,1223.44 v3@5463.7,1233.18 ; v3@5454.81,759.51 5457.66,762.36 5479.84,762.36 5479.84,800.72 5467.25,813.31 5467.25,821.37 v3(5454.26,834.36) ; v3@5454.81,1190.7 5457.66,1187.85 5479.84,1187.85 5479.84,1149.49 5467.25,1136.9 5467.25,1128.85 v3(5454.26,1115.86) ; v3(583.54,1622.21) v3(583.54,1660.57) v3(583.54,1641.23) v3(583.54,1622.21) ; v3(583.54,1903.71) v3(583.54,1865.36) v3(583.54,1884.69) v3(583.54,1903.71) ; v3(5454.26,834.36) v3(5454.26,872.71) v3(5454.26,853.38) v3(5454.26,834.36) ; v3(5454.26,1115.86) v3(5454.26,1077.5) v3(5454.26,1096.84) v3(5454.26,1115.86)
  L8 BOTTOM w20: v2(-94.21,3710.13) J1_4.12@7.32,3710.13 ; v2(-94.21,3810.13) J1_4.10@7.32,3810.13 ; v2(-94.21,3910.13) J1_4.8@7.32,3910.13 ; v2(-94.21,4010.13) J1_4.6@7.32,4010.13 ; v2(-94.21,4110.13) J1_4.4@7.32,4110.13 ; v2(-94.21,4210.13) J1_4.2@7.32,4210.13 ; v2(-94.21,4400.95) J1_1.12@7.32,4400.95 ; v2(-94.21,4500.95) J1_1.10@7.32,4500.95 ; v2(-94.21,4600.95) J1_1.8@7.32,4600.95 ; v2(-94.21,4700.95) J1_1.6@7.32,4700.95 ; v2(-94.21,4800.95) J1_1.4@7.32,4800.95 ; v2(-94.21,4900.95) J1_1.2@7.32,4900.95 ; v2(92.28,1703.18) R36.1@92.28,1743.05 ; v2(151.69,1913.4) R58.1@191.56,1913.4 ; v2(156.7,1739.74) C63.2@179.53,1739.74 ; v2(267.04,785.11) C9.2@297.71,785.11 ; R57.1@988.28,1813.25 v2(1028.15,1813.25) ; R55.1@1128.33,1618.2 v2(1168.2,1618.2) ; R20.1@1226.16,399.66 v2(1276.75,399.66) ; C136_4.2@1284.38,2983.06 1284.38,2980.41 v2(1313.54,2951.25) ; v2(1330.65,3422.31) 1360.26,3392.7 R85.2@1360.26,3374.45 ; v2(1565.04,3648.2) C181.2@1615.02,3648.2 ; v2(1565.04,3737.01) C184.2@1615.02,3737.01 ; v2(1757.5,3878.29) R139.1@1791.14,3878.29 ; C183.1@1783.09,3674.02 1783.09,3666.62 v2(1825.24,3624.48) ; v2(1841.77,3660.24) C182.2@1841.77,3693.88 ; v2(1878.45,-22.62) J2.2@1878.45,69.62 ; v2(1978.45,-22.62) J2.4@1978.45,69.62 ; v2(2078.45,-22.62) J2.6@2078.45,69.62 ; v2(2178.45,-22.62) J2.8@2178.45,69.62 ; C188.2@2220.98,3886.67 v2(2220.98,3920.31) ; C189.1@2280.22,3906.53 v2(2280.22,3950.95) ; C136_1.2@2454.38,3080.07 2454.38,3074.41 v2(2483.54,3045.25) ; v3(2706.84,2885.69) 2745.27,2885.69 2773.28,2857.68 C133_1.2@2773.28,2837.89 ; C136_3.2@3769.38,3080.07 3769.38,3074.41 v2(3798.54,3045.25) ; C130_3.2@3796.42,3338.44 3807.71,3349.73 v2(3872.5,3349.73) ; v2(4071.3,2955.26) 4094.55,2932.01 C133_3.2@4094.55,2878.26 ; v2(4138.47,3215.14) C199.2@4138.47,3185.83 C200.2@4179.47,3185.83 4179.47,3224.46 C198.2@4173.22,3230.71 v2(4173.22,3259.25) ; v2(4369.17,1978.16) C6_2.2@4322.67,1978.16 4322.67,1970.46 4347.05,1946.08 v2(4369.4,1946.08) ; C8_2.2@4431.59,2075.26 v2(4455.14,2075.26) ; v2(4451.14,2000.35) C7_2.2@4451.14,2031.28 ; v2@4716.45,2924.56 v2(4716.79,2924.22) ; v2(4912.9,941.32) R60.1@4912.9,981.19 ; v2(5027.42,956.89) C121.2@5050.26,956.89 ; C133_2.2@5050.19,2732.64 5074.3,2708.53 v2(5074.3,2695.45) ; R81.1@5859,1025.4 v2(5898.87,1025.4) ; J1_2.2@5989.68,3710.13 v2(6091.21,3710.13) ; J1_2.4@5989.68,3810.13 v2(6091.21,3810.13) ; J1_2.6@5989.68,3910.13 v2(6091.21,3910.13) ; J1_2.8@5989.68,4010.13 v2(6091.21,4010.13) ; J1_2.10@5989.68,4110.13 v2(6091.21,4110.13) ; J1_2.12@5989.68,4210.13 v2(6091.21,4210.13) ; J1_3.2@5989.68,4400.95 v2(6091.21,4400.95) ; J1_3.4@5989.68,4500.95 v2(6091.21,4500.95) ; J1_3.6@5989.68,4600.95 v2(6091.21,4600.95) ; J1_3.8@5989.68,4700.95 v2(6091.21,4700.95) ; J1_3.10@5989.68,4800.95 v2(6091.21,4800.95) ; J1_3.12@5989.68,4900.95 v2(6091.21,4900.95)
  L8 BOTTOM w25: C186.2@2220.98,3759.47 2276.12,3759.47 C187.1@2280.22,3755.36 2353.8,3755.36 C185.2@2359.46,3749.7 2404.17,3749.7 v2(2423.25,3768.78)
